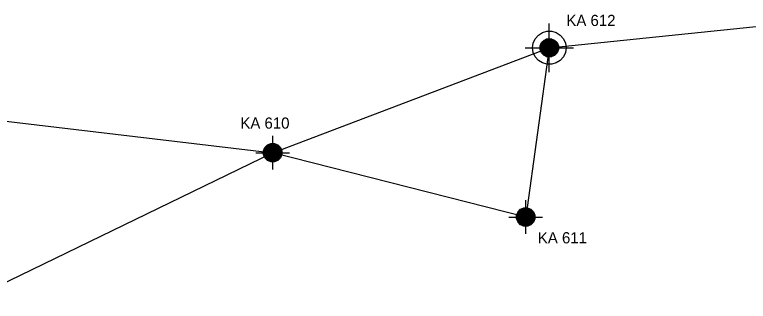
# Model space of a CAD drawing. Extents: x -346533 to -339969, y -1273090 to -1271585.
# Drawn here: x -341490.3 to -340998.8, y -1272101.3 to -1271909.1 of the extents above; entities that cross this region are included whole.
import ezdxf

# ---------------------------------------------------------------- set-up
doc = ezdxf.new("R2010")
doc.units = 0
for name, color, linetype in [('BP_11', 7, 'Continuous'), ('BP_12', 7, 'Continuous'), ('BP_14', 7, 'Continuous')]:
    doc.layers.add(name, color=color, linetype=linetype)

msp = doc.modelspace()

# ---------------------------------------------------------------- linework, layer by layer
at = {"layer": 'BP_11'}
for points in [[(-341132.14, -1271947.59), (-341132.14, -1271941.24), (-341132.14, -1271934.89), (-341132.14, -1271928.54), (-341132.14, -1271922.19), (-341132.14, -1271915.84), (-341132.14, -1271915.09)], [(-341132.14, -1271925.19), (-341130.94, -1271925.19), (-341128.69, -1271926.14), (-341126.99, -1271927.84), (-341126.04, -1271930.09), (-341126.04, -1271932.54), (-341126.99, -1271934.79), (-341128.69, -1271936.49), (-341130.94, -1271937.44), (-341133.39, -1271937.44), (-341135.64, -1271936.49), (-341137.34, -1271934.79), (-341138.29, -1271932.54), (-341138.29, -1271930.09), (-341137.34, -1271927.84), (-341135.64, -1271926.14), (-341133.39, -1271925.19), (-341132.19, -1271925.19), (-341130.39, -1271925.54), (-341133.99, -1271925.54), (-341134.79, -1271925.94), (-341129.59, -1271925.94), (-341128.79, -1271926.34), (-341135.14, -1271926.34), (-341135.59, -1271926.34), (-341135.99, -1271926.74), (-341129.64, -1271926.74), (-341128.39, -1271926.74), (-341127.99, -1271927.14), (-341134.34, -1271927.14), (-341136.39, -1271927.14), (-341136.79, -1271927.54), (-341130.44, -1271927.54), (-341127.59, -1271927.54), (-341127.19, -1271927.94), (-341133.54, -1271927.94), (-341137.19, -1271927.94), (-341137.19, -1271928.34), (-341130.84, -1271928.34), (-341127.19, -1271928.34), (-341126.79, -1271928.74), (-341133.14, -1271928.74), (-341137.59, -1271928.74), (-341137.59, -1271929.14), (-341131.24, -1271929.14), (-341126.79, -1271929.14), (-341126.79, -1271929.54), (-341133.14, -1271929.54), (-341137.59, -1271929.54), (-341137.99, -1271929.94), (-341131.64, -1271929.94), (-341126.39, -1271929.94), (-341126.39, -1271930.34), (-341132.74, -1271930.34), (-341137.99, -1271930.34), (-341137.99, -1271930.74), (-341131.64, -1271930.74), (-341126.39, -1271930.74), (-341126.39, -1271931.14), (-341132.74, -1271931.14), (-341137.99, -1271931.14), (-341137.99, -1271931.54), (-341131.64, -1271931.54), (-341126.39, -1271931.54), (-341126.39, -1271931.94), (-341132.74, -1271931.94), (-341137.99, -1271931.94), (-341137.99, -1271932.34), (-341131.64, -1271932.34), (-341126.39, -1271932.34), (-341126.39, -1271932.74), (-341132.74, -1271932.74), (-341137.99, -1271932.74), (-341137.99, -1271933.14), (-341131.64, -1271933.14), (-341126.39, -1271933.14), (-341126.79, -1271933.54), (-341133.14, -1271933.54), (-341137.59, -1271933.54), (-341137.59, -1271933.94), (-341131.24, -1271933.94), (-341126.79, -1271933.94), (-341127.19, -1271934.34), (-341133.54, -1271934.34), (-341137.19, -1271934.34), (-341137.19, -1271934.74), (-341130.84, -1271934.74), (-341127.19, -1271934.74), (-341127.59, -1271935.14), (-341133.94, -1271935.14), (-341136.79, -1271935.14), (-341136.39, -1271935.54), (-341130.04, -1271935.54), (-341127.99, -1271935.54), (-341128.39, -1271935.94), (-341134.74, -1271935.94), (-341135.99, -1271935.94), (-341135.59, -1271936.34), (-341129.24, -1271936.34), (-341128.79, -1271936.34)], [(-341148.39, -1271931.34), (-341142.04, -1271931.34), (-341135.69, -1271931.34), (-341129.34, -1271931.34), (-341122.99, -1271931.34), (-341116.64, -1271931.34), (-341115.89, -1271931.34)], [(-341128.79, -1271936.34), (-341129.59, -1271936.74), (-341134.79, -1271936.74), (-341133.99, -1271937.14), (-341130.39, -1271937.14)], [(-341317.45, -1272012.87), (-341317.45, -1272006.52), (-341317.45, -1272000.17), (-341317.45, -1271993.82), (-341317.45, -1271990.37)], [(-341317.45, -1271995.47), (-341316.25, -1271995.47), (-341314, -1271996.42), (-341312.3, -1271998.12), (-341311.35, -1272000.37), (-341311.35, -1272002.82), (-341312.3, -1272005.07), (-341314, -1272006.77), (-341316.25, -1272007.72), (-341318.7, -1272007.72), (-341320.95, -1272006.77), (-341322.65, -1272005.07), (-341323.6, -1272002.82), (-341323.6, -1272000.37), (-341322.65, -1271998.12), (-341320.95, -1271996.42), (-341318.7, -1271995.47), (-341317.5, -1271995.47), (-341315.7, -1271995.82), (-341319.3, -1271995.82), (-341320.1, -1271996.22), (-341314.9, -1271996.22), (-341314.1, -1271996.62), (-341320.45, -1271996.62), (-341320.9, -1271996.62), (-341321.3, -1271997.02), (-341314.95, -1271997.02), (-341313.7, -1271997.02), (-341313.3, -1271997.42), (-341319.65, -1271997.42), (-341321.7, -1271997.42), (-341322.1, -1271997.82), (-341315.75, -1271997.82), (-341312.9, -1271997.82), (-341312.5, -1271998.22), (-341318.85, -1271998.22), (-341322.5, -1271998.22), (-341322.5, -1271998.62), (-341316.15, -1271998.62), (-341312.5, -1271998.62), (-341312.1, -1271999.02), (-341318.45, -1271999.02), (-341322.9, -1271999.02), (-341322.9, -1271999.42), (-341316.55, -1271999.42), (-341312.1, -1271999.42), (-341311.7, -1271999.82), (-341318.05, -1271999.82), (-341323.3, -1271999.82), (-341323.3, -1272000.22), (-341316.95, -1272000.22), (-341311.7, -1272000.22), (-341311.7, -1272000.62), (-341318.05, -1272000.62), (-341323.3, -1272000.62), (-341323.3, -1272001.02), (-341316.95, -1272001.02), (-341311.7, -1272001.02), (-341311.7, -1272001.42), (-341318.05, -1272001.42), (-341323.3, -1272001.42), (-341323.3, -1272001.82), (-341316.95, -1272001.82), (-341311.7, -1272001.82), (-341311.7, -1272002.22), (-341318.05, -1272002.22), (-341323.3, -1272002.22), (-341323.3, -1272002.62), (-341316.95, -1272002.62), (-341311.7, -1272002.62), (-341311.7, -1272003.02), (-341318.05, -1272003.02), (-341323.3, -1272003.02), (-341323.3, -1272003.42), (-341316.95, -1272003.42), (-341311.7, -1272003.42), (-341312.1, -1272003.82), (-341318.45, -1272003.82), (-341322.9, -1272003.82), (-341322.9, -1272004.22), (-341316.55, -1272004.22), (-341312.1, -1272004.22), (-341312.5, -1272004.62), (-341318.85, -1272004.62), (-341322.5, -1272004.62), (-341322.5, -1272005.02), (-341316.15, -1272005.02), (-341312.5, -1272005.02), (-341312.9, -1272005.42), (-341319.25, -1272005.42), (-341322.1, -1272005.42), (-341321.7, -1272005.82), (-341315.35, -1272005.82), (-341313.3, -1272005.82), (-341313.7, -1272006.22), (-341320.05, -1272006.22), (-341321.3, -1272006.22), (-341320.9, -1272006.62), (-341314.55, -1272006.62), (-341314.1, -1272006.62)], [(-341328.7, -1272001.62), (-341322.35, -1272001.62), (-341316, -1272001.62), (-341309.65, -1272001.62), (-341306.2, -1272001.62)], [(-341314.1, -1272006.62), (-341314.9, -1272007.02), (-341320.1, -1272007.02), (-341319.3, -1272007.42), (-341315.7, -1272007.42)], [(-341147.91, -1272056.03), (-341147.91, -1272049.68), (-341147.91, -1272043.33), (-341147.91, -1272036.98), (-341147.91, -1272033.53)], [(-341147.91, -1272038.63), (-341146.71, -1272038.63), (-341144.46, -1272039.58), (-341142.76, -1272041.28), (-341141.81, -1272043.53), (-341141.81, -1272045.98), (-341142.76, -1272048.23), (-341144.46, -1272049.93), (-341146.71, -1272050.88), (-341149.16, -1272050.88), (-341151.41, -1272049.93), (-341153.11, -1272048.23), (-341154.06, -1272045.98), (-341154.06, -1272043.53), (-341153.11, -1272041.28), (-341151.41, -1272039.58), (-341149.16, -1272038.63), (-341147.96, -1272038.63), (-341146.16, -1272038.98), (-341149.76, -1272038.98), (-341150.56, -1272039.38), (-341145.36, -1272039.38), (-341144.56, -1272039.78), (-341150.91, -1272039.78), (-341151.36, -1272039.78), (-341151.76, -1272040.18), (-341145.41, -1272040.18), (-341144.16, -1272040.18), (-341143.76, -1272040.58), (-341150.11, -1272040.58), (-341152.16, -1272040.58), (-341152.56, -1272040.98), (-341146.21, -1272040.98), (-341143.36, -1272040.98), (-341142.96, -1272041.38), (-341149.31, -1272041.38), (-341152.96, -1272041.38), (-341152.96, -1272041.78), (-341146.61, -1272041.78), (-341142.96, -1272041.78), (-341142.56, -1272042.18), (-341148.91, -1272042.18), (-341153.36, -1272042.18), (-341153.36, -1272042.58), (-341147.01, -1272042.58), (-341142.56, -1272042.58), (-341142.16, -1272042.98), (-341148.51, -1272042.98), (-341153.76, -1272042.98), (-341153.76, -1272043.38), (-341147.41, -1272043.38), (-341142.16, -1272043.38), (-341142.16, -1272043.78), (-341148.51, -1272043.78), (-341153.76, -1272043.78), (-341153.76, -1272044.18), (-341147.41, -1272044.18), (-341142.16, -1272044.18), (-341142.16, -1272044.58), (-341148.51, -1272044.58), (-341153.76, -1272044.58), (-341153.76, -1272044.98), (-341147.41, -1272044.98), (-341142.16, -1272044.98), (-341142.16, -1272045.38), (-341148.51, -1272045.38), (-341153.76, -1272045.38), (-341153.76, -1272045.78), (-341147.41, -1272045.78), (-341142.16, -1272045.78), (-341142.16, -1272046.18), (-341148.51, -1272046.18), (-341153.76, -1272046.18), (-341153.76, -1272046.58), (-341147.41, -1272046.58), (-341142.16, -1272046.58), (-341142.56, -1272046.98), (-341148.91, -1272046.98), (-341153.36, -1272046.98), (-341153.36, -1272047.38), (-341147.01, -1272047.38), (-341142.56, -1272047.38), (-341142.96, -1272047.78), (-341149.31, -1272047.78), (-341152.96, -1272047.78), (-341152.96, -1272048.18), (-341146.61, -1272048.18), (-341142.96, -1272048.18), (-341143.36, -1272048.58), (-341149.71, -1272048.58), (-341152.56, -1272048.58), (-341152.16, -1272048.98), (-341145.81, -1272048.98), (-341143.76, -1272048.98), (-341144.16, -1272049.38), (-341150.51, -1272049.38), (-341151.76, -1272049.38), (-341151.36, -1272049.78), (-341145.01, -1272049.78), (-341144.56, -1272049.78)], [(-341159.16, -1272044.78), (-341152.81, -1272044.78), (-341146.46, -1272044.78), (-341140.11, -1272044.78), (-341136.66, -1272044.78)], [(-341144.56, -1272049.78), (-341145.36, -1272050.18), (-341150.56, -1272050.18), (-341149.76, -1272050.58), (-341146.16, -1272050.58)]]:
    msp.add_lwpolyline(points, dxfattribs=at)
for points in [[(-341130.54, -1271920.19), (-341127.49, -1271921.09), (-341124.79, -1271922.84), (-341122.69, -1271925.24), (-341121.34, -1271928.14), (-341120.89, -1271931.29), (-341121.34, -1271934.44), (-341122.69, -1271937.34), (-341124.79, -1271939.74), (-341127.49, -1271941.49), (-341130.54, -1271942.39), (-341133.74, -1271942.39), (-341136.79, -1271941.49), (-341139.49, -1271939.74), (-341141.59, -1271937.34), (-341142.94, -1271934.44), (-341143.39, -1271931.29), (-341142.94, -1271928.14), (-341141.59, -1271925.24), (-341139.49, -1271922.84), (-341136.79, -1271921.09), (-341133.74, -1271920.19)], [(-341316.25, -1271995.47), (-341314, -1271996.42), (-341312.3, -1271998.12), (-341311.35, -1272000.37), (-341311.35, -1272002.82), (-341312.3, -1272005.07), (-341314, -1272006.77), (-341316.25, -1272007.72), (-341318.7, -1272007.72), (-341320.95, -1272006.77), (-341322.65, -1272005.07), (-341323.6, -1272002.82), (-341323.6, -1272000.37), (-341322.65, -1271998.12), (-341320.95, -1271996.42), (-341318.7, -1271995.47)], [(-341146.71, -1272038.63), (-341144.46, -1272039.58), (-341142.76, -1272041.28), (-341141.81, -1272043.53), (-341141.81, -1272045.98), (-341142.76, -1272048.23), (-341144.46, -1272049.93), (-341146.71, -1272050.88), (-341149.16, -1272050.88), (-341151.41, -1272049.93), (-341153.11, -1272048.23), (-341154.06, -1272045.98), (-341154.06, -1272043.53), (-341153.11, -1272041.28), (-341151.41, -1272039.58), (-341149.16, -1272038.63)]]:
    msp.add_lwpolyline(points, close=True, dxfattribs=at)
at = {"layer": 'BP_14'}
for p, q in [((-341132.14, -1271931.34), (-340941.47, -1271911.52)), ((-341317.45, -1272001.62), (-341132.14, -1271931.34)), ((-341132.14, -1271931.34), (-341147.91, -1272044.78)), ((-341606.7, -1271967.48), (-341317.45, -1272001.62)), ((-341317.45, -1272001.62), (-341522.51, -1272101.3)), ((-341147.91, -1272044.78), (-341317.45, -1272001.62))]:
    msp.add_line(p, q, dxfattribs=at)

# ---------------------------------------------------------------- texts
at = {"layer": 'BP_12'}
for s, p in [('KA 612', (-341120.71, -1271916.7)), ('KA 610', (-341339.1, -1271985.52)), ('KA 611', (-341139.83, -1272062.43))]:
    msp.add_text(s, height=7.5, dxfattribs=at).set_placement(p)

doc.saveas('drawing.dxf')
